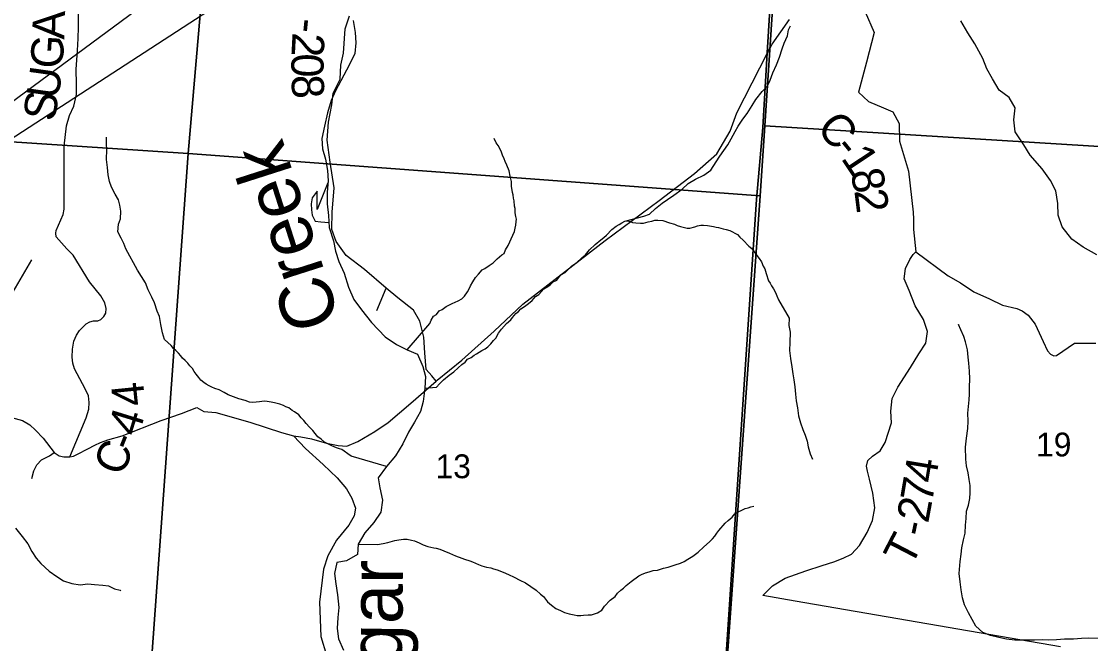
# Model space of a CAD drawing. Extents: x 0 to 34, y 0 to 22.
# Drawn here: x 5.391 to 7.274, y 16.459 to 17.554 of the extents above; entities that cross this region are included whole.
import ezdxf

# ---------------------------------------------------------------- set-up
doc = ezdxf.new("R2010")
doc.units = 0
for name, color, linetype in [('GM_X_Corporation', 7, 'Continuous'), ('GM_X_County_Road', 7, 'Continuous'), ('GM_X_County_Road_Text', 7, 'Continuous'), ('GM_X_Minor_River', 7, 'Continuous'), ('GM_X_Minor_River_Text', 7, 'Continuous'), ('GM_X_Section_Text', 7, 'Continuous'), ('GM_X_State_Route', 7, 'Continuous'), ('GM_X_Township_Road', 7, 'Continuous'), ('GM_X_Township_Road_Text', 7, 'Continuous'), ('SH_Text', 7, 'Continuous')]:
    doc.layers.add(name, color=color, linetype=linetype)

msp = doc.modelspace()

# ---------------------------------------------------------------- linework, layer by layer
at = {"layer": 'GM_X_Corporation'}
for points in [[(8.9, 16.2015), (8.9, 20.2763), (8.59, 20.3005), (8.3805, 20.3169), (8.0028, 20.34), (6.9032, 20.4198), (6.8961, 20.3303), (6.835, 19.4037), (6.824, 19.3005), (6.7876, 18.7583), (6.7629, 18.3924), (6.7536, 18.2991), (6.7043, 17.4985), (6.6962, 17.3669), (6.6852, 17.2401), (6.6249, 16.3344), (7.5782, 16.28), (7.7162, 16.2721), (7.873, 16.2628)], [(4.7598, 18.4308), (5.775, 18.3681), (5.6845, 17.321), (4.6804, 17.3872)], [(6.7676, 18.3985), (7.864, 18.3242), (7.7921, 17.3025), (6.6999, 17.3699), (6.7615, 18.3053)], [(5.775, 18.3681), (6.7615, 18.3053), (6.6999, 17.3699), (6.6918, 17.2464), (5.6845, 17.321)], [(4.6804, 17.3872), (5.6845, 17.321), (5.612, 16.3148), (5.6072, 16.3154), (4.6087, 16.3871)], [(6.6999, 17.3699), (7.7921, 17.3025), (7.7202, 16.2762), (6.6272, 16.3394), (6.6918, 17.2464)], [(5.6845, 17.321), (6.6918, 17.2464), (6.6272, 16.3394), (6.621, 16.2504), (5.612, 16.3148)]]:
    msp.add_lwpolyline(points, close=True, dxfattribs=at)
msp.add_lwpolyline([(3.3441, 14.1), (5.4627, 14.1), (5.4763, 14.3006), (5.4833, 14.4122), (5.4893, 14.5091), (5.5809, 15.9822), (5.6022, 16.3258), (5.6497, 16.3069), (5.8351, 16.2952), (5.9321, 16.289), (6.6163, 16.2457), (6.6249, 16.3344), (6.6852, 17.2401), (6.6962, 17.3669), (6.7043, 17.4985), (6.7536, 18.2991)], dxfattribs=at)
at = {"layer": 'GM_X_County_Road'}
for points in [[(5.4762, 16.7875), (5.5048, 16.8563), (5.5097, 16.8714), (5.5104, 16.883), (5.5091, 16.8946), (5.5032, 16.9072), (5.4845, 16.9425), (5.4814, 16.9525), (5.48, 16.9628), (5.4806, 16.977), (5.483, 16.9908), (5.4876, 17.0015), (5.4932, 17.0095), (5.5046, 17.0215), (5.5113, 17.025), (5.5177, 17.0266), (5.5254, 17.027), (5.5306, 17.029), (5.5359, 17.0342), (5.5394, 17.04), (5.5403, 17.0483), (5.5377, 17.0585), (5.5309, 17.071), (5.5105, 17.0955), (5.4819, 17.1421), (5.4708, 17.1532), (5.452, 17.1744), (5.4517, 17.1807), (5.4523, 17.1858), (5.4642, 17.2136), (5.466, 17.2234), (5.4661, 17.3338), (5.4702, 17.3696), (5.4754, 17.3881), (5.4834, 17.4045), (5.4878, 17.4247), (5.4878, 17.4436), (5.487, 17.4689), (5.4895, 17.5023), (5.4907, 17.5233), (5.4915, 17.5433), (5.4915, 17.6057)], [(6.861, 17.6075), (6.8924, 17.5342), (6.8792, 17.482), (6.8648, 17.429), (6.8828, 17.4128), (6.909, 17.4016)], [(6.909, 17.4016), (6.9255, 17.3945), (6.9367, 17.3737), (6.937, 17.3429), (6.9527, 17.2902), (6.9613, 17.2177), (6.9615, 17.2059)], [(6.9615, 17.2059), (6.9619, 17.1873), (6.9657, 17.148), (7.0231, 17.1057), (7.0448, 17.0937), (7.0678, 17.078), (7.0956, 17.0653), (7.1185, 17.0545), (7.144, 17.0486), (7.1534, 17.0446), (7.1635, 17.0366), (7.1762, 17.0208), (7.1901, 16.9901), (7.1979, 16.9738), (7.2028, 16.9683), (7.209, 16.9652), (7.2135, 16.9656), (7.2453, 16.9872), (7.2829, 16.9875)], [(5.8701, 16.8242), (5.891, 16.8023), (5.9225, 16.7742), (5.9468, 16.7506), (5.9631, 16.7309), (5.9729, 16.7149), (5.979, 16.697), (5.9767, 16.6834), (5.9672, 16.667), (5.9459, 16.6408), (5.9303, 16.6131), (5.9231, 16.59), (5.9158, 16.5319), (5.918, 16.4715), (5.9279, 16.4388), (5.9313, 16.4187), (5.9313, 16.3944), (5.9308, 16.3677), (5.9294, 16.3385), (5.9297, 16.311), (5.9312, 16.2975), (5.9323, 16.2885), (5.9328, 16.2817)]]:
    msp.add_lwpolyline(points, dxfattribs=at)
at = {"layer": 'GM_X_Minor_River'}
for points in [[(5.9748, 17.5553), (5.9786, 17.534), (5.98, 17.5158), (5.9777, 17.4968), (5.9686, 17.4778), (5.9533, 17.449), (5.9442, 17.4316), (5.9366, 17.4142), (5.9297, 17.3929), (5.9243, 17.3694), (5.9197, 17.3474), (5.9212, 17.3292), (5.9264, 17.311), (5.9301, 17.2912), (5.9308, 17.273), (5.9293, 17.2533), (5.9292, 17.2328), (5.9314, 17.2123), (5.9329, 17.191), (5.9404, 17.1675), (5.9441, 17.1492), (5.9501, 17.131), (5.9591, 17.1105), (5.9666, 17.0862), (5.9764, 17.0641), (5.9899, 17.0459), (6.0073, 17.0238), (6.0314, 16.9987), (6.0511, 16.985), (6.07, 16.9758), (6.0881, 16.9682), (6.0979, 16.9462), (6.1024, 16.9287), (6.1015, 16.9082), (6.0984, 16.8847), (6.0938, 16.8673), (6.0832, 16.8483), (6.0725, 16.8309), (6.0626, 16.8105), (6.0497, 16.7893), (6.0337, 16.7703), (6.0193, 16.7506), (6.0223, 16.7332), (6.0268, 16.7112), (6.0237, 16.6899), (6.0115, 16.6718), (5.9955, 16.6536), (5.9841, 16.6339), (5.9826, 16.6157), (5.9636, 16.6044), (5.9462, 16.6014), (5.9423, 16.5825), (5.9445, 16.5643), (5.9475, 16.5445), (5.9497, 16.5225), (5.9481, 16.5051)], [(7.2846, 17.1431), (7.2605, 17.1561), (7.2408, 17.1706), (7.2235, 17.1919), (7.2167, 17.2124), (7.216, 17.2329), (7.2123, 17.2557), (7.2033, 17.2739), (7.1882, 17.2944), (7.1671, 17.318), (7.1558, 17.3363), (7.1407, 17.3591), (7.1385, 17.3804), (7.1409, 17.4016), (7.1303, 17.4199), (7.1129, 17.4328), (7.1009, 17.4526), (7.0911, 17.4701), (7.0836, 17.4883), (7.07, 17.5142), (7.0572, 17.5332), (7.0452, 17.5545)], [(6.4557, 17.2024), (6.4871, 17.2106), (6.4969, 17.2147), (6.5075, 17.2242), (6.5189, 17.2337), (6.5287, 17.2405), (6.5397, 17.2481), (6.5545, 17.2583), (6.5651, 17.2686), (6.578, 17.2758), (6.5927, 17.283), (6.6048, 17.2921), (6.6143, 17.3065), (6.6207, 17.3167), (6.6275, 17.3262), (6.6351, 17.3361), (6.6408, 17.3471), (6.648, 17.3596), (6.6529, 17.369), (6.6612, 17.3816), (6.6688, 17.3918), (6.6779, 17.4058), (6.6843, 17.4161), (6.6953, 17.4305), (6.7044, 17.44), (6.7093, 17.4502), (6.7142, 17.4631), (6.7207, 17.4771), (6.726, 17.4908), (6.7305, 17.5052), (6.7343, 17.5154), (6.74, 17.5279), (6.7415, 17.5389), (6.7449, 17.5458)], [(5.6543, 16.9833), (5.6426, 16.994), (5.6395, 17.0057), (5.6365, 17.0202), (5.6339, 17.0342), (5.6301, 17.0437), (5.6252, 17.0585), (5.6206, 17.0683), (5.6142, 17.0812), (5.6093, 17.0938), (5.6021, 17.1048), (5.595, 17.1161), (5.5885, 17.1287), (5.5817, 17.1404), (5.5745, 17.1533), (5.5715, 17.1628), (5.5666, 17.1723), (5.5606, 17.1833), (5.5617, 17.1966), (5.5651, 17.2061), (5.5662, 17.2194), (5.564, 17.23), (5.5617, 17.2398), (5.556, 17.2497), (5.5496, 17.2622), (5.5458, 17.2721), (5.5436, 17.2835), (5.5424, 17.2968), (5.5409, 17.3104), (5.5413, 17.3279), (5.5409, 17.3378), (5.5409, 17.3499)], [(6.07, 16.9758), (6.1099, 17.0223), (6.1123, 17.028), (6.1166, 17.0348), (6.1216, 17.0381), (6.1266, 17.0445), (6.1316, 17.0467), (6.1389, 17.0519), (6.1434, 17.0541), (6.1496, 17.0574), (6.1602, 17.0618), (6.1664, 17.0655), (6.171, 17.07), (6.1764, 17.0775), (6.1799, 17.0842), (6.1815, 17.0884), (6.1858, 17.0952), (6.1905, 17.1027), (6.1955, 17.1087), (6.2025, 17.1162), (6.2067, 17.1191), (6.2144, 17.1243), (6.2216, 17.1288), (6.2286, 17.1359), (6.2367, 17.1429), (6.2409, 17.1452), (6.2436, 17.1516), (6.2479, 17.1591), (6.2562, 17.1776), (6.2593, 17.184), (6.2606, 17.1897), (6.2614, 17.195), (6.2623, 17.2014), (6.2624, 17.2056), (6.2613, 17.2102), (6.2603, 17.217), (6.2601, 17.2243), (6.2594, 17.2285), (6.2584, 17.2376), (6.2573, 17.2426), (6.2567, 17.2483), (6.2556, 17.2525), (6.2539, 17.2635), (6.2537, 17.2719), (6.2516, 17.2814), (6.2495, 17.2906), (6.2459, 17.3009), (6.2426, 17.307), (6.2411, 17.3116), (6.2382, 17.3185), (6.236, 17.3235), (6.2342, 17.3285), (6.2302, 17.3354), (6.2269, 17.34), (6.2232, 17.3477)], [(5.9305, 17.2693), (5.9115, 17.2227), (5.9115, 17.255), (5.9031, 17.2432), (5.9009, 17.2326), (5.9016, 17.222), (5.9031, 17.2125), (5.908, 17.2019), (5.9179, 17.2011), (5.9322, 17.2), (5.9315, 17.2004)], [(6.1015, 16.9082), (6.122, 16.91), (6.127, 16.9157), (6.1343, 16.9231), (6.1439, 16.9313), (6.1524, 16.9369), (6.1597, 16.944), (6.1662, 16.95), (6.172, 16.954), (6.1766, 16.9593), (6.1827, 16.9622), (6.1881, 16.9663), (6.1923, 16.9685), (6.2015, 16.9748), (6.2076, 16.9774), (6.2122, 16.9811), (6.2172, 16.9863), (6.2223, 16.9923), (6.2261, 16.9964), (6.2312, 17.0051), (6.2363, 17.0118), (6.2451, 17.0223), (6.2525, 17.0287), (6.2559, 17.0328), (6.2617, 17.0399), (6.266, 17.0429), (6.2702, 17.0481), (6.2767, 17.0518), (6.284, 17.0574), (6.2902, 17.0626), (6.2964, 17.0693), (6.3021, 17.0731), (6.3106, 17.0828), (6.3179, 17.0872), (6.3225, 17.0906), (6.3275, 17.0954), (6.3336, 17.0984), (6.3406, 17.1074), (6.3482, 17.1118), (6.3602, 17.1234), (6.3686, 17.1286), (6.3782, 17.1383), (6.384, 17.1431), (6.391, 17.1517), (6.401, 17.1611), (6.411, 17.1693), (6.4167, 17.1733), (6.421, 17.1775), (6.4306, 17.1875), (6.4379, 17.1931), (6.4436, 17.1961), (6.4482, 17.199), (6.4532, 17.202), (6.4578, 17.2027), (6.4627, 17.2018), (6.4672, 17.1999), (6.4729, 17.1994), (6.4808, 17.1985), (6.4861, 17.1984), (6.4945, 17.2009), (6.5009, 17.2023), (6.5063, 17.2037), (6.5116, 17.204), (6.5203, 17.2035), (6.5323, 17.1991), (6.541, 17.1967), (6.5455, 17.1947), (6.5512, 17.1927), (6.5564, 17.1915), (6.5632, 17.1899), (6.5681, 17.1898), (6.5765, 17.1923), (6.5815, 17.1937), (6.5872, 17.1948), (6.5917, 17.1951), (6.5989, 17.1946), (6.6095, 17.1929), (6.6144, 17.1917), (6.6185, 17.1912), (6.6268, 17.1888), (6.6317, 17.1876), (6.6381, 17.1856), (6.6517, 17.1785), (6.6558, 17.1742), (6.6621, 17.1684), (6.6718, 17.1584), (6.677, 17.1541), (6.6811, 17.1483), (6.6859, 17.1418), (6.6899, 17.1364), (6.694, 17.1306), (6.6969, 17.123), (6.6998, 17.1184), (6.7023, 17.11), (6.7063, 17.0974), (6.7092, 17.0931), (6.7118, 17.0882), (6.7151, 17.0832), (6.7188, 17.0766), (6.7214, 17.0705), (6.7239, 17.0636)], [(6.7239, 17.0636), (6.7429, 17.0316), (6.7425, 17.0187), (6.7444, 17.0066), (6.744, 16.9888), (6.7436, 16.9744), (6.7452, 16.9607), (6.7474, 16.946), (6.7493, 16.9335), (6.7512, 16.9232), (6.7527, 16.9107), (6.7538, 16.8978), (6.7554, 16.8861), (6.7576, 16.8739), (6.7595, 16.8595), (6.7629, 16.8474), (6.7667, 16.8357), (6.7709, 16.8258), (6.7746, 16.8152), (6.7765, 16.805), (6.7799, 16.7928), (6.7837, 16.7834), (6.7837, 16.7837)], [(7.2889, 16.4677), (7.2703, 16.4685), (7.2575, 16.4681), (7.2435, 16.4669), (7.2276, 16.4666), (7.2136, 16.4654), (7.1988, 16.4651), (7.1886, 16.4658), (7.1746, 16.4647), (7.1572, 16.4651), (7.1401, 16.4647), (7.1258, 16.4666), (7.1121, 16.4696), (7.0974, 16.473), (7.0841, 16.4787), (7.0716, 16.4893), (7.0584, 16.5128), (7.0516, 16.5272), (7.0478, 16.5393), (7.0455, 16.5533), (7.0437, 16.5674), (7.0422, 16.5825), (7.0437, 16.6034), (7.0456, 16.6162), (7.0467, 16.6272), (7.0497, 16.6413), (7.0528, 16.653), (7.0535, 16.667), (7.0543, 16.6788), (7.055, 16.6917), (7.0588, 16.7023), (7.0607, 16.714), (7.0615, 16.7239), (7.0615, 16.7368), (7.0596, 16.7474), (7.0581, 16.7591), (7.0551, 16.7716), (7.0539, 16.7834), (7.0532, 16.8046), (7.0551, 16.8205), (7.0577, 16.8376), (7.0581, 16.8504), (7.0577, 16.8645), (7.0589, 16.8758), (7.06, 16.8876), (7.0604, 16.8978), (7.0604, 16.9103), (7.0612, 16.9247), (7.0604, 16.938), (7.0593, 16.952), (7.0581, 16.963), (7.057, 16.9755), (7.0532, 16.9896), (7.0502, 16.9994), (7.0449, 17.0108), (7.0408, 17.0203), (7.0404, 17.0191)], [(6.0337, 16.7703), (6.0337, 16.7703), (5.9717, 16.7887), (5.9654, 16.793), (5.9594, 16.7977), (5.9549, 16.8004), (5.9507, 16.8013), (5.9459, 16.8032), (5.9417, 16.8052), (5.9372, 16.8068), (5.9293, 16.8111), (5.9248, 16.8135), (5.9185, 16.8185), (5.9129, 16.8228), (5.9084, 16.8286), (5.904, 16.834), (5.898, 16.8398), (5.8924, 16.8459), (5.8884, 16.8513), (5.8832, 16.856), (5.8791, 16.8614), (5.872, 16.8668), (5.8678, 16.8688), (5.8619, 16.8734), (5.8562, 16.8754), (5.8521, 16.8778), (5.8461, 16.8802), (5.8367, 16.8826), (5.8306, 16.8835), (5.8238, 16.8847), (5.8181, 16.8852), (5.8102, 16.8842), (5.8041, 16.8835), (5.7984, 16.8829), (5.7924, 16.8837), (5.7848, 16.8865), (5.7735, 16.8897), (5.7641, 16.8929), (5.7547, 16.8965), (5.748, 16.9008), (5.7393, 16.9051), (5.7314, 16.9079), (5.7262, 16.9103), (5.7216, 16.9123), (5.7164, 16.9154), (5.7123, 16.9185), (5.7071, 16.9224), (5.703, 16.927), (5.6985, 16.9332), (5.6948, 16.9374), (5.6919, 16.9428), (5.6874, 16.9478), (5.6841, 16.9521), (5.6793, 16.9571), (5.6744, 16.961), (5.6714, 16.9652), (5.6674, 16.9698), (5.6625, 16.9745), (5.6584, 16.9783), (5.6543, 16.9833)], [(5.9841, 16.6339), (6.0182, 16.6333), (6.0277, 16.6351), (6.0361, 16.6368), (6.0403, 16.6379), (6.0483, 16.64), (6.0555, 16.6414), (6.0635, 16.6424), (6.0703, 16.6427), (6.0775, 16.6407), (6.0831, 16.6395), (6.0914, 16.6359), (6.0982, 16.6327), (6.1064, 16.6299), (6.1121, 16.6287), (6.117, 16.6275), (6.1215, 16.6266), (6.1279, 16.625), (6.1347, 16.6219), (6.1445, 16.6179), (6.155, 16.6135), (6.1667, 16.6092), (6.1712, 16.6076), (6.1806, 16.6047), (6.1851, 16.6028), (6.196, 16.598), (6.2017, 16.596), (6.21, 16.5936), (6.2175, 16.592), (6.2224, 16.5907), (6.2284, 16.5887), (6.239, 16.5848), (6.2484, 16.5804), (6.2585, 16.5757), (6.2683, 16.5706), (6.2784, 16.5659), (6.2882, 16.5596), (6.2975, 16.553), (6.305, 16.5457), (6.3102, 16.5418), (6.3135, 16.5368), (6.3172, 16.5322), (6.3243, 16.5263), (6.3318, 16.5209), (6.34, 16.517), (6.3472, 16.5138), (6.3555, 16.5114), (6.3642, 16.5093), (6.3698, 16.5085), (6.3759, 16.5084), (6.3808, 16.5087), (6.3888, 16.5093), (6.3948, 16.5096), (6.3998, 16.511), (6.4055, 16.5128), (6.4132, 16.518), (6.4178, 16.5247), (6.4275, 16.5352), (6.4363, 16.5419), (6.4406, 16.5475), (6.4464, 16.5528), (6.4513, 16.5565), (6.456, 16.5613), (6.4648, 16.5684), (6.4782, 16.578), (6.4828, 16.5802), (6.4901, 16.5835), (6.4962, 16.585), (6.5034, 16.5875), (6.511, 16.5881), (6.5213, 16.5918), (6.53, 16.5931), (6.5422, 16.5975), (6.5517, 16.6007), (6.5582, 16.6033), (6.5644, 16.6074), (6.5732, 16.6125), (6.5828, 16.6196), (6.5924, 16.6293), (6.6028, 16.6379), (6.6078, 16.6435), (6.612, 16.648), (6.6152, 16.6532), (6.619, 16.6581), (6.6299, 16.6708), (6.6356, 16.6753), (6.6422, 16.6816), (6.6472, 16.6872), (6.6533, 16.6906), (6.6583, 16.6931), (6.6652, 16.6964), (6.6709, 16.6979), (6.6754, 16.6993), (6.6808, 16.7004)], [(5.3807, 16.6619), (5.392, 16.6471), (5.4022, 16.6345), (5.4093, 16.6208), (5.4169, 16.6094), (5.4252, 16.5999), (5.4395, 16.5862), (5.4531, 16.5767), (5.4652, 16.5694), (5.4799, 16.5648), (5.4943, 16.5621), (5.5076, 16.5643), (5.5193, 16.5631), (5.534, 16.5616), (5.5443, 16.5604), (5.5548, 16.5554), (5.5647, 16.5527), (5.5662, 16.552)], [(5.9481, 16.5051), (5.9466, 16.4854), (5.9495, 16.4671), (5.9578, 16.4474)]]:
    msp.add_lwpolyline(points, dxfattribs=at)
at = {"layer": 'GM_X_State_Route'}
msp.add_lwpolyline([(5.3563, 16.8616), (5.3927, 16.8515), (5.4058, 16.8439), (5.4159, 16.8344), (5.429, 16.8203), (5.4486, 16.7949), (5.4574, 16.7893), (5.4653, 16.7877), (5.4762, 16.7875), (5.4828, 16.7889), (5.4895, 16.792), (5.5081, 16.8017), (5.5201, 16.8083), (5.5302, 16.8129), (5.543, 16.8176), (5.5684, 16.8246), (5.6372, 16.8512), (5.673, 16.8637), (5.6998, 16.874), (5.7123, 16.867), (5.7331, 16.8652), (5.7931, 16.8486), (5.849, 16.8305), (5.8701, 16.8242), (5.883, 16.8229), (5.9019, 16.8189), (5.9283, 16.8117), (5.9487, 16.8073), (5.9638, 16.8064), (5.9833, 16.8142), (6.0134, 16.832), (6.0367, 16.8481), (6.0765, 16.8818), (6.1215, 16.9207), (6.1232, 16.9222), (6.1665, 16.9574), (6.2231, 17.0083), (6.2741, 17.0559), (6.419, 17.1681), (6.5142, 17.2384), (6.5761, 17.2859), (6.6156, 17.3208), (6.6392, 17.3604), (6.6505, 17.3925), (6.6909, 17.4721), (6.7045, 17.498), (6.7126, 17.5133), (6.7434, 17.557)], dxfattribs=at)
at = {"layer": 'GM_X_Township_Road'}
for p, q in [((6.0168, 17.0449), (6.0334, 17.0844)), ((7.2207, 16.4531), (6.7536, 16.5335))]:
    msp.add_line(p, q, dxfattribs=at)
for points in [[(6.1215, 16.9207), (6.1136, 16.9299), (6.1038, 16.9409), (6.1011, 16.9705), (6.0996, 16.9979), (6.0925, 17.0264), (6.0811, 17.0454), (6.0537, 17.067), (6.0334, 17.0844), (5.9949, 17.1172), (5.963, 17.1419), (5.9452, 17.1663), (5.9376, 17.1875), (5.938, 17.2179), (5.9415, 17.2609), (5.9343, 17.3057), (5.929, 17.3445), (5.9317, 17.376), (5.9374, 17.4068), (5.9397, 17.4274), (5.9519, 17.4517), (5.9534, 17.4764), (5.958, 17.4977), (5.9607, 17.5402), (5.9687, 17.5634)], [(6.881, 16.7625), (6.8792, 16.7708), (6.8815, 16.781), (6.8898, 16.7886), (6.9032, 16.7981), (6.9119, 16.8125), (6.9229, 16.8475), (6.9218, 16.8676), (6.9241, 16.89), (6.934, 16.9098), (6.9564, 16.9447), (6.9709, 16.9687), (6.9834, 16.9877), (6.9865, 17.0078), (6.9793, 17.0291), (6.9649, 17.0534), (6.9543, 17.0804), (6.9452, 17.1005), (6.9479, 17.1188), (6.9551, 17.1347), (6.9612, 17.1435), (6.9657, 17.148)], [(5.3325, 16.9189), (5.333, 16.9221), (5.3381, 16.958), (5.3555, 17.0248), (5.3763, 17.0775), (5.4092, 17.1339)], [(5.4092, 16.7491), (5.4128, 16.7628), (5.418, 16.7735), (5.4263, 16.7824), (5.4403, 16.7894), (5.4486, 16.7949)], [(6.7536, 16.5335), (6.6967, 16.5433), (6.7134, 16.5604), (6.7358, 16.5741), (6.7723, 16.587), (6.8008, 16.5961), (6.8213, 16.6029), (6.838, 16.609), (6.8525, 16.6162), (6.8666, 16.6314), (6.8799, 16.6542), (6.8898, 16.6754), (6.8936, 16.6978), (6.8902, 16.7237), (6.8841, 16.748), (6.881, 16.7625)]]:
    msp.add_lwpolyline(points, dxfattribs=at)
at = {"layer": 'SH_Text'}
msp.add_lwpolyline([(4.6475, 16.8758), (5.8902, 17.7932), (5.8902, 17.6825)], close=True, dxfattribs=at)

# ---------------------------------------------------------------- texts
at = {"layer": 'GM_X_County_Road_Text'}
for s, rotation, p in [('A', 88.2576, (5.4664, 17.5213)), ('G', 86.2843, (5.463, 17.4693)), ('U', 82.0417, (5.4557, 17.4152)), ('S', 80.7083, (5.4492, 17.3759)), ('C', 310.096, (6.7892, 17.3653)), ('-', 309.2096, (6.8191, 17.3298)), ('1', 303.5999, (6.833, 17.3129)), ('8', 282.191, (6.8502, 17.2889)), ('2', 277.1533, (6.8574, 17.256)), ('4', 95.7674, (5.6092, 16.8791)), ('4', 72.8156, (5.5964, 16.8211)), ('C', 68.1149, (5.5687, 16.7513)), ('-', 68.4668, (5.5863, 16.795))]:
    msp.add_text(s, height=0.0568, rotation=rotation, dxfattribs=at).set_placement(p)
at = {"layer": 'GM_X_Minor_River_Text'}
for s, height, rotation, p in [('Creek', 0.09474, 107.753, (5.9529, 17.0268)), ('Sugar', 0.09469, 89.4916, (6.0598, 16.2678))]:
    msp.add_text(s, height=height, rotation=rotation, dxfattribs=at).set_placement(p)
at = {"layer": 'GM_X_Section_Text'}
for s, p in [('19', (7.1776, 16.7882)), ('13', (6.1201, 16.7499))]:
    msp.add_text(s, height=0.04186, rotation=0, dxfattribs=at).set_placement(p)
at = {"layer": 'GM_X_Township_Road_Text'}
for s, rotation, p in [('-', 264.3347, (5.8709, 17.5609)), ('2', 267.0309, (5.8684, 17.5348)), ('0', 269.1156, (5.8665, 17.4976)), ('8', 272.8571, (5.866, 17.4585)), ('4', 80.5428, (7, 16.7394)), ('7', 80.3334, (6.9941, 16.7047)), ('2', 79.4819, (6.9875, 16.6693)), ('-', 78.0268, (6.9824, 16.645)), ('T', 62.5643, (6.9572, 16.5916))]:
    msp.add_text(s, height=0.0568, rotation=rotation, dxfattribs=at).set_placement(p)

doc.saveas('drawing.dxf')
